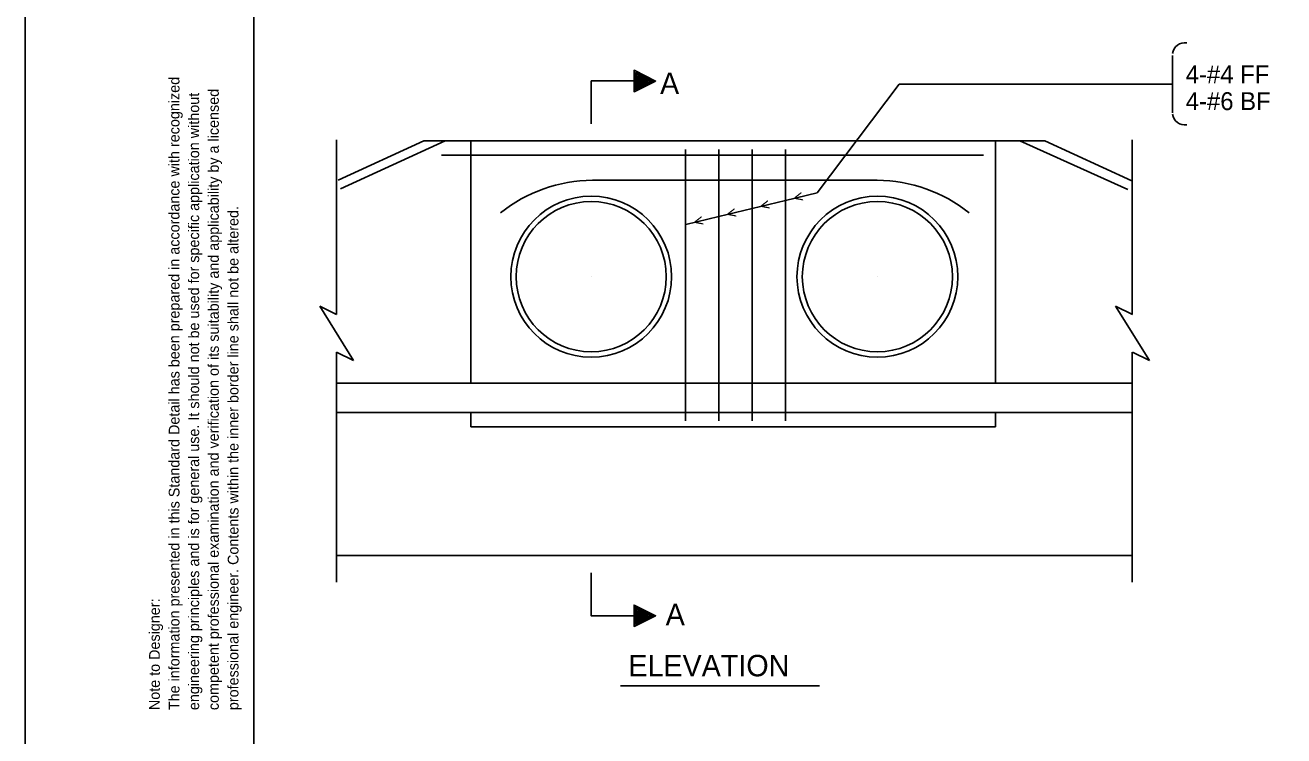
# Model space of a CAD drawing. Extents: x -0.08 to 2.83, y -0.03 to 1.92.
# Drawn here: x 0 to 0.917, y 0.576 to 1.094 of the extents above; entities that cross this region are included whole.
import ezdxf

# ---------------------------------------------------------------- set-up
doc = ezdxf.new("R2010")
doc.units = 0
for name, color, linetype in [('50', 7, 'Continuous'), ('51', 7, 'Continuous'), ('55', 7, 'Continuous'), ('57', 7, 'Continuous'), ('63', 7, 'Continuous')]:
    doc.layers.add(name, color=color, linetype=linetype)

msp = doc.modelspace()

# ---------------------------------------------------------------- linework, layer by layer
at = {"layer": '50'}
for p, q in [((0.22674, 1.0107), (0.22674, 0.88345)), ((0.22813, 0.98128), (0.29048, 1.00992)), ((0.74285, 1.00992), (0.29048, 1.00992)), ((0.32475, 1.00992), (0.32475, 0.83284)), ((0.70685, 1.00992), (0.70685, 0.83284)), ((0.72464, 1.00992), (0.80334, 0.9744)), ((0.74285, 1.00992), (0.80641, 0.98072)), ((0.80663, 1.0107), (0.80663, 0.88345)), ((0.41241, 0.91096), (0.41241, 0.91096)), ((0.62091, 0.91096), (0.62091, 0.91096)), ((0.21459, 0.88959), (0.22693, 0.88345)), ((0.21459, 0.88959), (0.23926, 0.84985)), ((0.79448, 0.88959), (0.80682, 0.88345)), ((0.79448, 0.88959), (0.81915, 0.84985)), ((0.22693, 0.86972), (0.22693, 0.86972)), ((0.80682, 0.86972), (0.80682, 0.86972)), ((0.22674, 0.85599), (0.22674, 0.68846)), ((0.22693, 0.85599), (0.23926, 0.84985)), ((0.80663, 0.85599), (0.80663, 0.68846)), ((0.80682, 0.85599), (0.81915, 0.84985)), ((0.80663, 0.83334), (0.22674, 0.83334)), ((0.80663, 0.812), (0.22674, 0.812)), ((0.32475, 0.812), (0.32475, 0.80158)), ((0.70685, 0.80158), (0.70685, 0.812)), ((0.70685, 0.80158), (0.32475, 0.80158)), ((0.80663, 0.70784), (0.22674, 0.70784))]:
    msp.add_line(p, q, dxfattribs=at)
msp.add_lwpolyline([(0.22977, 0.975), (0.3061, 1.00992)], dxfattribs=at)
for centre, radius in [((0.41241, 0.91096), 0.05859), ((0.41241, 0.91096), 0.05469), ((0.62091, 0.91096), 0.05859), ((0.62091, 0.91096), 0.05469)]:
    msp.add_circle(centre, radius, dxfattribs=at)
at = {"layer": '51'}
for p, q in [((0.48109, 0.806), (0.48109, 1.00359)), ((0.50542, 0.806), (0.50542, 1.00359)), ((0.52974, 0.806), (0.52974, 1.00359)), ((0.55407, 0.806), (0.55407, 1.00359)), ((0.30341, 0.9995), (0.69823, 0.9995)), ((0.41333, 0.98125), (0.62079, 0.98125))]:
    msp.add_line(p, q, dxfattribs=at)
for centre, start, end in [((0.41429, 0.87228), 90.50764, 128.60403), ((0.61983, 0.87228), 51.39597, 89.49236)]:
    msp.add_arc(centre, 0.10897, start, end, dxfattribs=at)
at = {"layer": '55'}
for p, q in [((0.83599, 1.03035), (0.83599, 1.07205)), ((0.57693, 0.97194), (0.63678, 1.0512)), ((0.63678, 1.0512), (0.83599, 1.0512)), ((0.52974, 0.96055), (0.55395, 0.9664)), ((0.55407, 0.96643), (0.57693, 0.97194)), ((0.4814, 0.9489), (0.50542, 0.95469)), ((0.50542, 0.9547), (0.5296, 0.96052))]:
    msp.add_line(p, q, dxfattribs=at)
for points in [[(0.4124, 1.0223), (0.4124, 1.05355), (0.44365, 1.05355), (0.44365, 1.06128), (0.45928, 1.05347), (0.44365, 1.04565), (0.44365, 1.05344), (0.44482, 1.05355), (0.44482, 1.0597), (0.45732, 1.05345), (0.44482, 1.0472), (0.44482, 1.05344), (0.44575, 1.05355), (0.44575, 1.05843), (0.45575, 1.05343), (0.44575, 1.04843), (0.44575, 1.05344), (0.44668, 1.05355), (0.44668, 1.05701), (0.45373, 1.05349), (0.44668, 1.04997), (0.44668, 1.05344), (0.44766, 1.05355), (0.44766, 1.05599), (0.45262, 1.0535), (0.44766, 1.05102), (0.44766, 1.05344), (0.44823, 1.05355), (0.44823, 1.05495), (0.45112, 1.05351), (0.44823, 1.05207), (0.44823, 1.05344), (0.44878, 1.05355), (0.44878, 1.05408), (0.44986, 1.05355), (0.44878, 1.053), (0.44878, 1.05344)], [(0.4124, 0.6951), (0.4124, 0.66385), (0.44365, 0.66385), (0.44365, 0.65613), (0.45928, 0.66394), (0.44365, 0.67175), (0.44365, 0.66397), (0.44482, 0.66385), (0.44482, 0.65771), (0.45732, 0.66396), (0.44482, 0.67021), (0.44482, 0.66397), (0.44575, 0.66385), (0.44575, 0.65898), (0.45575, 0.66398), (0.44575, 0.66898), (0.44575, 0.66397), (0.44668, 0.66385), (0.44668, 0.6604), (0.45373, 0.66392), (0.44668, 0.66744), (0.44668, 0.66397), (0.44766, 0.66385), (0.44766, 0.66142), (0.45262, 0.66391), (0.44766, 0.66639), (0.44766, 0.66397), (0.44823, 0.66385), (0.44823, 0.66245), (0.45112, 0.6639), (0.44823, 0.66534), (0.44823, 0.66397), (0.44878, 0.66385), (0.44878, 0.66333), (0.44986, 0.66386), (0.44878, 0.6644), (0.44878, 0.66397)]]:
    msp.add_lwpolyline(points, dxfattribs=at)
for centre, start, end in [((0.84492, 1.07242), 81.38054, 173.15738), ((0.84492, 1.0305), 186.84262, 278.61946), ((0.84492, 1.0305), 186.84262, 278.61946)]:
    msp.add_arc(centre, 0.009, start, end, dxfattribs=at)
at = {"layer": '57'}
msp.add_line((0.43366, 0.61295), (0.57869, 0.61295), dxfattribs=at)
at = {"layer": '63'}
msp.add_line((0, 0), (0, 1.83333), dxfattribs=at)
msp.add_lwpolyline([(0.16668, 0.06244), (0.16668, 1.77077), (2.72918, 1.77077), (2.72918, 0.10411), (2.56251, 0.10411), (2.56251, 0.14578), (2.07387, 0.14578), (2.07387, 0.06244)], close=True, dxfattribs=at)

# ---------------------------------------------------------------- texts
at = {"layer": '55'}
for s, height, rotation, p in [('The information presented in this Standard Detail has been prepared in accordance with recognized', 0.0078167, 90, (0.11243, 0.59517)), ('competent professional examination and verification of its suitability and applicability by a licensed', 0.00781665, 90, (0.14108, 0.59517)), ('engineering principles and is for general use. It should not be used for specific application without', 0.00781665, 90, (0.12676, 0.59517)), ('>', 0.00867, 193.51142, (0.56571, 0.97369)), ('>', 0.00868, 193.59134, (0.54138, 0.96782)), ('professional engineer. Contents within the inner border line shall not be altered.', 0.0078167, 90, (0.15541, 0.59517)), ('>', 0.00867, 193.54708, (0.49304, 0.95616)), ('>', 0.00867, 193.51142, (0.51706, 0.96195)), ('Note to Designer:', 0.0078167, 90, (0.09811, 0.59517))]:
    msp.add_text(s, height=height, rotation=rotation, dxfattribs=at).set_placement(p)
at = {"layer": '57'}
for s, height, p in [('4-#4 FF', 0.013017, (0.84556, 1.05185)), ('A', 0.01562, (0.46258, 1.04399)), ('4-#6 BF', 0.013017, (0.84556, 1.03233)), ('A', 0.01562, (0.46668, 0.65705)), ('ELEVATION', 0.015625, (0.43949, 0.61981))]:
    msp.add_text(s, height=height, dxfattribs=at).set_placement(p)

doc.saveas('drawing.dxf')
